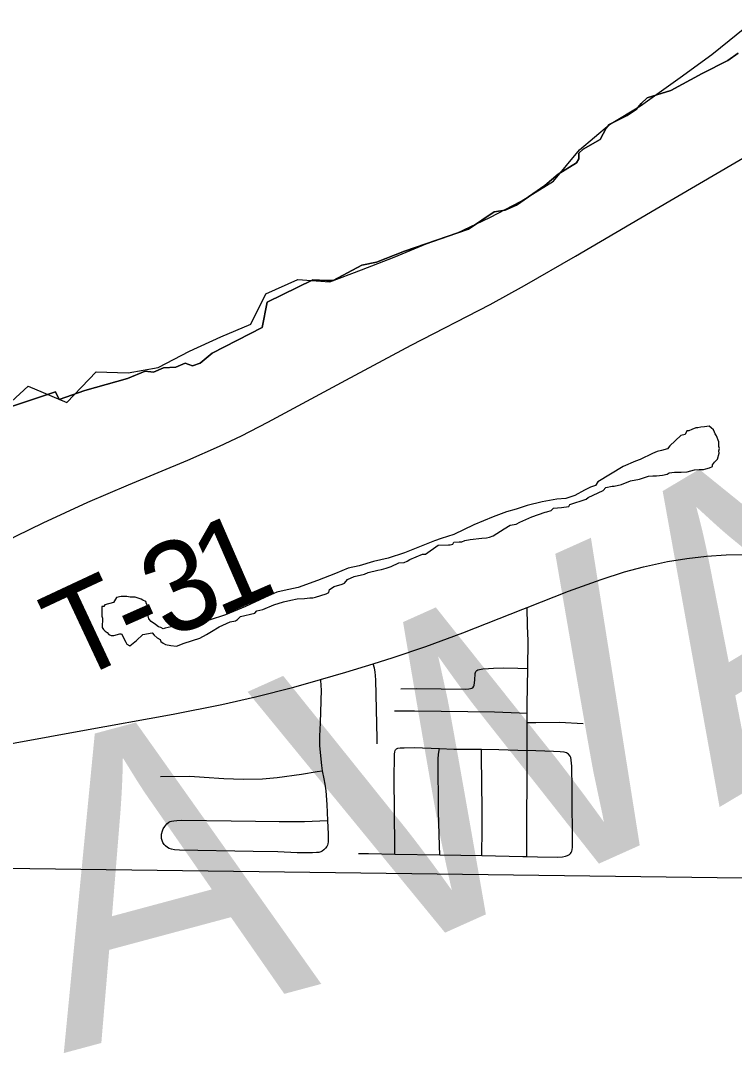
# Model space of a CAD drawing. Extents: x 0 to 34, y 0 to 22.
# Drawn here: x 4.7988 to 5.0235, y 18.3789 to 18.7064 of the extents above; entities that cross this region are included whole.
import ezdxf

# ---------------------------------------------------------------- set-up
doc = ezdxf.new("R2010")
doc.units = 0
for name, color, linetype in [('GM_X_Corporation', 7, 'Continuous'), ('GM_X_County_Text', 7, 'Continuous'), ('GM_X_Major_Lake', 7, 'Continuous'), ('GM_X_Minor_River', 7, 'Continuous'), ('GM_X_State_Route', 7, 'Continuous'), ('GM_X_Township_Road', 7, 'Continuous'), ('GM_X_Township_Road_Text', 7, 'Continuous')]:
    doc.layers.add(name, color=color, linetype=linetype)

msp = doc.modelspace()

# ---------------------------------------------------------------- linework, layer by layer
at = {"layer": 'GM_X_Corporation'}
for points in [[(5.02476, 18.69621), (5.0215, 18.69393), (5.01346, 18.68978), (5.00354, 18.6845), (4.99607, 18.68215), (4.9942, 18.68036), (4.99265, 18.67849), (4.98981, 18.67654), (4.98412, 18.67378), (4.98314, 18.67256), (4.98128, 18.66906), (4.97591, 18.66597), (4.97453, 18.66467), (4.97453, 18.66297), (4.97388, 18.66166), (4.96803, 18.65809), (4.96389, 18.65451), (4.95489, 18.64837), (4.95137, 18.64671), (4.94787, 18.64622), (4.93986, 18.64075), (4.91967, 18.63387), (4.91089, 18.63038), (4.90618, 18.62948), (4.89716, 18.62461), (4.89505, 18.62461), (4.89074, 18.62477), (4.87636, 18.61778), (4.87481, 18.60981), (4.85904, 18.60169), (4.8553, 18.5986), (4.85287, 18.5977), (4.85059, 18.5986), (4.84766, 18.5973), (4.84377, 18.59705), (4.8406, 18.59567), (4.838, 18.596), (4.83247, 18.59372), (4.81898, 18.58998), (4.81093, 18.58714), (4.80979, 18.5895), (4.75916, 18.57276)], [(4.75916, 18.57276), (4.80979, 18.5895), (4.81093, 18.58714), (4.81898, 18.58998), (4.83247, 18.59372), (4.838, 18.596), (4.8406, 18.59567), (4.84377, 18.59705), (4.84766, 18.5973), (4.85059, 18.5986), (4.85287, 18.5977), (4.8553, 18.5986), (4.85904, 18.60169), (4.87481, 18.60981), (4.87636, 18.61778), (4.89074, 18.62477), (4.89505, 18.62461), (4.89716, 18.62461), (4.90618, 18.62948), (4.91089, 18.63038), (4.91967, 18.63387), (4.93986, 18.64075), (4.94787, 18.64622), (4.95137, 18.64671), (4.95489, 18.64837), (4.96389, 18.65451), (4.96803, 18.65809), (4.97388, 18.66166), (4.97453, 18.66297), (4.97453, 18.66467), (4.97591, 18.66597), (4.98128, 18.66906), (4.98314, 18.67256), (4.98412, 18.67378), (4.98981, 18.67654), (4.99265, 18.67849), (4.9942, 18.68036), (4.99607, 18.68215), (5.00354, 18.6845), (5.01346, 18.68978), (5.0215, 18.69393), (5.02476, 18.69621)]]:
    msp.add_lwpolyline(points, dxfattribs=at)
msp.add_lwpolyline([(5.2907, 18.43288), (5.30482, 18.43261), (5.30041, 17.93698), (5.29864, 17.93686), (4.7909, 17.94084), (4.79371, 18.43949)], close=True, dxfattribs=at)
at = {"layer": 'GM_X_Major_Lake'}
for points in [[(5.00645, 18.68857), (5.01649, 18.69579), (5.02958, 18.70643)], [(4.79051, 18.58161), (4.80113, 18.5913), (4.81326, 18.58618), (4.82255, 18.59586), (4.8326, 18.59548), (4.84208, 18.5972), (4.85194, 18.60232), (4.8618, 18.60688), (4.87128, 18.61087), (4.87601, 18.62037), (4.88606, 18.62493), (4.89611, 18.62417), (4.90616, 18.62797), (4.9164, 18.63196), (4.92644, 18.63614), (4.93611, 18.63956), (4.94654, 18.6445), (4.9564, 18.64963), (4.96664, 18.6559), (4.97479, 18.66578), (4.98427, 18.67376), (4.99394, 18.67964), (5.00645, 18.68857)]]:
    msp.add_lwpolyline(points, dxfattribs=at)
at = {"layer": 'GM_X_Minor_River'}
for points in [[(4.85028, 18.51028), (4.85523, 18.51195), (4.85733, 18.51307), (4.85886, 18.51401), (4.86134, 18.51551), (4.86477, 18.51701), (4.86648, 18.51737), (4.86705, 18.51775), (4.86801, 18.51869), (4.87257, 18.5198), (4.87315, 18.52055), (4.87505, 18.52092), (4.87848, 18.52241), (4.88153, 18.52334), (4.88381, 18.52389), (4.8859, 18.52425), (4.88818, 18.52443), (4.88989, 18.5246), (4.89084, 18.52459), (4.8916, 18.52478), (4.89503, 18.52589), (4.89579, 18.52627), (4.89599, 18.52721), (4.89752, 18.52815), (4.89999, 18.52889), (4.90075, 18.52927), (4.90171, 18.5304), (4.90381, 18.53133), (4.90704, 18.53207), (4.90818, 18.53263), (4.91123, 18.53337), (4.91237, 18.53355), (4.91389, 18.53392), (4.91541, 18.53447), (4.91789, 18.5356), (4.9196, 18.53577), (4.92055, 18.53614), (4.92132, 18.53671), (4.92532, 18.53839), (4.92627, 18.53838), (4.93028, 18.5412), (4.93351, 18.54136), (4.93408, 18.54136), (4.93484, 18.54154), (4.93522, 18.54211), (4.93693, 18.54229), (4.93769, 18.54228), (4.93864, 18.54265), (4.94036, 18.54302), (4.94397, 18.54337), (4.94549, 18.54355), (4.94644, 18.54374), (4.94758, 18.54411), (4.95102, 18.54636), (4.95292, 18.54748), (4.95483, 18.54785), (4.95597, 18.54841), (4.95978, 18.55009), (4.96397, 18.55158), (4.96454, 18.55176), (4.96587, 18.55213), (4.96664, 18.55289), (4.96911, 18.55306), (4.97139, 18.55342), (4.97177, 18.55399), (4.97691, 18.55566), (4.97749, 18.55622), (4.98225, 18.55847), (4.98302, 18.55941), (4.98511, 18.55977), (4.98568, 18.55977), (4.98797, 18.56032), (4.99082, 18.56144), (4.99367, 18.56199), (4.99653, 18.56292), (4.99786, 18.5631), (4.999, 18.56309), (5.0009, 18.56326), (5.00242, 18.56363), (5.003, 18.56401), (5.00471, 18.56418), (5.0068, 18.56417), (5.0087, 18.56435), (5.01098, 18.5649), (5.0125, 18.56508), (5.01383, 18.56507), (5.01459, 18.56525), (5.01573, 18.56562), (5.01668, 18.56599), (5.01669, 18.56656), (5.01726, 18.56732), (5.01822, 18.56826), (5.0188, 18.57016), (5.01862, 18.57092), (5.01882, 18.57167), (5.01863, 18.57225), (5.01864, 18.57376), (5.0179, 18.57567), (5.01752, 18.57624), (5.01734, 18.57681), (5.01696, 18.57757)], [(5.01696, 18.57757), (5.01621, 18.57815), (5.01564, 18.57872), (5.01412, 18.57854), (5.01298, 18.57836), (5.01203, 18.57818), (5.01146, 18.57819), (5.01013, 18.57762), (5.00917, 18.57725), (5.0086, 18.57726), (5.00802, 18.57612), (5.00669, 18.57575)], [(5.00669, 18.57575), (5.00325, 18.57255), (5.00248, 18.57161), (5.00058, 18.57105), (4.99925, 18.57068), (4.99772, 18.57012), (4.99391, 18.56825), (4.99239, 18.5677), (4.98858, 18.56601), (4.98056, 18.56114), (4.9798, 18.56), (4.97827, 18.55945), (4.97637, 18.55851), (4.97332, 18.55683), (4.97046, 18.5559), (4.96761, 18.55573), (4.96305, 18.55481), (4.95829, 18.55371), (4.95486, 18.5526), (4.95182, 18.55167), (4.94763, 18.55018), (4.94153, 18.54757), (4.93524, 18.54458), (4.93124, 18.54328), (4.92915, 18.54254), (4.92496, 18.54086), (4.91963, 18.53881), (4.91448, 18.53714), (4.90992, 18.53603), (4.90535, 18.53474), (4.90193, 18.53401), (4.89793, 18.53233), (4.89221, 18.53009), (4.88612, 18.52786), (4.88174, 18.52694), (4.87946, 18.52639), (4.87565, 18.52471), (4.86955, 18.52191), (4.86326, 18.5193), (4.85812, 18.51763), (4.85489, 18.51708), (4.85204, 18.51615), (4.84956, 18.5156), (4.8488, 18.5158), (4.84614, 18.51544), (4.84424, 18.51507), (4.84367, 18.51489), (4.84291, 18.51527), (4.84216, 18.51547), (4.84121, 18.51623), (4.83989, 18.51719), (4.83914, 18.51796), (4.83895, 18.51891), (4.83896, 18.51967), (4.83878, 18.52081), (4.83879, 18.52195), (4.83841, 18.52271), (4.83823, 18.52347), (4.83728, 18.52386), (4.83672, 18.52424), (4.83482, 18.52482), (4.8333, 18.52484), (4.83216, 18.52503), (4.83045, 18.52505), (4.82893, 18.52468), (4.82797, 18.52317), (4.82531, 18.52243), (4.82492, 18.52186), (4.82435, 18.52186), (4.82434, 18.52035), (4.82433, 18.51883), (4.82452, 18.51826), (4.82449, 18.51522), (4.82487, 18.51465), (4.82543, 18.51407), (4.826, 18.51369), (4.82657, 18.51311), (4.82732, 18.51273), (4.82808, 18.51272), (4.82998, 18.51328), (4.83055, 18.51327), (4.83112, 18.51213), (4.83149, 18.51137), (4.83186, 18.51061), (4.83224, 18.51003), (4.83318, 18.50946), (4.83529, 18.51115), (4.8372, 18.51304), (4.84024, 18.51358), (4.84081, 18.51282), (4.84175, 18.51205), (4.8427, 18.51148), (4.84288, 18.5109), (4.84364, 18.51033), (4.84439, 18.50994), (4.8461, 18.50955), (4.84781, 18.50935), (4.85028, 18.51028)]]:
    msp.add_lwpolyline(points, dxfattribs=at)
at = {"layer": 'GM_X_State_Route'}
msp.add_lwpolyline([(4.78718, 18.4771), (4.81777, 18.4827), (4.84683, 18.48797), (4.86209, 18.49097), (4.87272, 18.49338), (4.88477, 18.49648), (4.89318, 18.49889), (4.90122, 18.50119), (4.90977, 18.50383), (4.91609, 18.50577), (4.92641, 18.50927), (4.93808, 18.51358), (4.95688, 18.52102), (4.95826, 18.52156), (4.97133, 18.52672), (4.98155, 18.53042), (4.98892, 18.53279), (4.99491, 18.53441), (5.00247, 18.53607), (5.00858, 18.53704), (5.01475, 18.53772), (5.02093, 18.53817), (5.02712, 18.53831)], dxfattribs=at)
at = {"layer": 'GM_X_Township_Road'}
for p, q in [((4.9583, 18.48537), (4.9583, 18.48831)), ((4.91658, 18.44389), (4.93075, 18.44363)), ((4.93075, 18.44363), (4.94401, 18.44339))]:
    msp.add_line(p, q, dxfattribs=at)
for points in [[(4.74311, 18.51842), (4.74433, 18.51891), (4.7585, 18.52486), (4.77123, 18.53059), (4.77956, 18.53475), (4.79741, 18.5442), (4.80582, 18.54823), (4.81994, 18.55473), (4.83278, 18.56026), (4.85142, 18.56801), (4.86137, 18.57236), (4.86836, 18.57568), (4.87662, 18.57996), (4.90123, 18.59322), (4.9218, 18.60419), (4.94661, 18.61705), (4.95747, 18.62307), (4.9735, 18.63229), (4.99897, 18.64719), (5.03732, 18.66961)], [(4.95847, 18.50238), (4.95859, 18.5111), (4.95844, 18.51576), (4.95826, 18.52156)], [(4.91104, 18.47865), (4.9111, 18.48018), (4.91063, 18.49877), (4.91057, 18.49999), (4.91045, 18.50126), (4.91021, 18.5025), (4.90977, 18.50383)], [(4.91855, 18.49599), (4.92349, 18.496), (4.93896, 18.49587), (4.93992, 18.49592), (4.94048, 18.49601), (4.94091, 18.49614), (4.94118, 18.4963), (4.94154, 18.49679), (4.94163, 18.49713), (4.94179, 18.49864), (4.94188, 18.50076), (4.94199, 18.50112), (4.94217, 18.50143), (4.94246, 18.5017), (4.9428, 18.50193), (4.94328, 18.50206), (4.94429, 18.50224), (4.94613, 18.50238), (4.94768, 18.50244), (4.95077, 18.50259), (4.9554, 18.50246), (4.95847, 18.50238)], [(4.9583, 18.48831), (4.95831, 18.49088), (4.95847, 18.50238)], [(4.89318, 18.49889), (4.89333, 18.4968), (4.8934, 18.49577), (4.89333, 18.49206), (4.89306, 18.48526), (4.89284, 18.48107), (4.89292, 18.47797), (4.89347, 18.47179), (4.89372, 18.47008)], [(4.9165, 18.48898), (4.9228, 18.48896), (4.94802, 18.48868), (4.9559, 18.4884), (4.9583, 18.48831)], [(4.95827, 18.47654), (4.95829, 18.47999), (4.9583, 18.48537)], [(4.9583, 18.48537), (4.96099, 18.48537), (4.96849, 18.4854), (4.97598, 18.48506)], [(4.91658, 18.44389), (4.91657, 18.44616), (4.91642, 18.46811), (4.91651, 18.47446), (4.91656, 18.47535), (4.91661, 18.47612), (4.9167, 18.47648), (4.91685, 18.47677), (4.91709, 18.47704), (4.91753, 18.47723), (4.91832, 18.47735), (4.91952, 18.47735), (4.92268, 18.47743), (4.93071, 18.4771)], [(4.93075, 18.44363), (4.93067, 18.44645), (4.93037, 18.4573), (4.93026, 18.47389), (4.93036, 18.47523), (4.93046, 18.476), (4.93071, 18.4771)], [(4.93071, 18.4771), (4.93522, 18.47692), (4.9439, 18.47689)], [(4.94401, 18.44339), (4.94404, 18.44503), (4.94413, 18.45028), (4.94414, 18.45787), (4.94393, 18.47458), (4.9439, 18.47689)], [(4.9439, 18.47689), (4.94933, 18.47687), (4.95827, 18.47654)], [(4.95815, 18.44313), (4.95815, 18.44577), (4.95827, 18.47654)], [(4.95815, 18.44313), (4.96158, 18.44305), (4.96786, 18.4429), (4.96942, 18.44304), (4.97035, 18.44319), (4.97105, 18.44341), (4.9716, 18.44374), (4.9719, 18.44401), (4.97215, 18.44436), (4.97232, 18.44477), (4.97242, 18.44518), (4.97252, 18.44606), (4.97252, 18.44736), (4.97253, 18.45048), (4.97246, 18.45988), (4.97247, 18.46525), (4.97236, 18.47078), (4.97232, 18.47165), (4.97226, 18.47239), (4.97219, 18.47353), (4.97202, 18.47432), (4.9718, 18.47475), (4.97134, 18.47533), (4.97101, 18.4756), (4.97064, 18.47581), (4.96993, 18.47599), (4.96869, 18.47607), (4.96657, 18.47622), (4.95827, 18.47654)], [(4.8428, 18.46836), (4.85201, 18.46838), (4.8566, 18.46816), (4.86272, 18.46769), (4.86885, 18.46748), (4.87499, 18.46758), (4.87958, 18.46796), (4.88722, 18.46907), (4.8922, 18.46985), (4.89372, 18.47008)], [(4.89372, 18.47008), (4.89427, 18.46755), (4.8946, 18.46589), (4.89487, 18.46378), (4.89523, 18.4595), (4.89543, 18.45442)], [(4.89543, 18.45442), (4.8956, 18.4502), (4.89562, 18.44861), (4.8956, 18.44778), (4.89548, 18.44711), (4.89538, 18.4467), (4.89517, 18.44625), (4.8948, 18.44577), (4.89422, 18.4452), (4.8937, 18.44482), (4.89328, 18.44458), (4.89272, 18.44442), (4.89191, 18.44434), (4.89066, 18.44428), (4.88871, 18.44426), (4.88586, 18.44428), (4.87978, 18.44461), (4.87204, 18.44466), (4.84875, 18.44506), (4.8472, 18.44522), (4.84626, 18.44538), (4.84556, 18.44562), (4.84502, 18.44597), (4.84443, 18.44643), (4.84397, 18.44691), (4.84354, 18.44755), (4.8433, 18.44815), (4.84316, 18.44882), (4.84314, 18.44938), (4.84316, 18.45016), (4.8434, 18.45124), (4.84365, 18.45186), (4.84413, 18.45261), (4.8448, 18.45337), (4.84545, 18.45391), (4.84583, 18.45412), (4.84623, 18.45426), (4.84698, 18.45439), (4.84795, 18.45448), (4.8495, 18.45458), (4.86505, 18.4544), (4.87271, 18.45421), (4.88014, 18.4541), (4.88817, 18.4541), (4.89543, 18.45442)], [(4.90519, 18.44411), (4.90832, 18.44404), (4.91658, 18.44389)], [(4.94401, 18.44339), (4.95688, 18.44316), (4.95815, 18.44313)]]:
    msp.add_lwpolyline(points, dxfattribs=at)

# ---------------------------------------------------------------- texts
at = {"layer": 'GM_X_County_Text'}
for s, rotation, p in [('A', 30.7829, (5.01868, 18.45857)), ('W', 24.1741, (4.90851, 18.40837)), ('A', 15.0384, (4.81211, 18.38111))]:
    msp.add_text(s, height=0.0947, rotation=rotation, dxfattribs=at).set_placement(p)
at = {"layer": 'GM_X_Township_Road_Text'}
for s, rotation, p in [('1', 23.515, (4.86093, 18.51842)), ('3', 23.5942, (4.8449, 18.51142)), ('T', 25.0911, (4.81517, 18.49776)), ('-', 23.8935, (4.83427, 18.50671))]:
    msp.add_text(s, height=0.02841, rotation=rotation, dxfattribs=at).set_placement(p)

doc.saveas('drawing.dxf')
